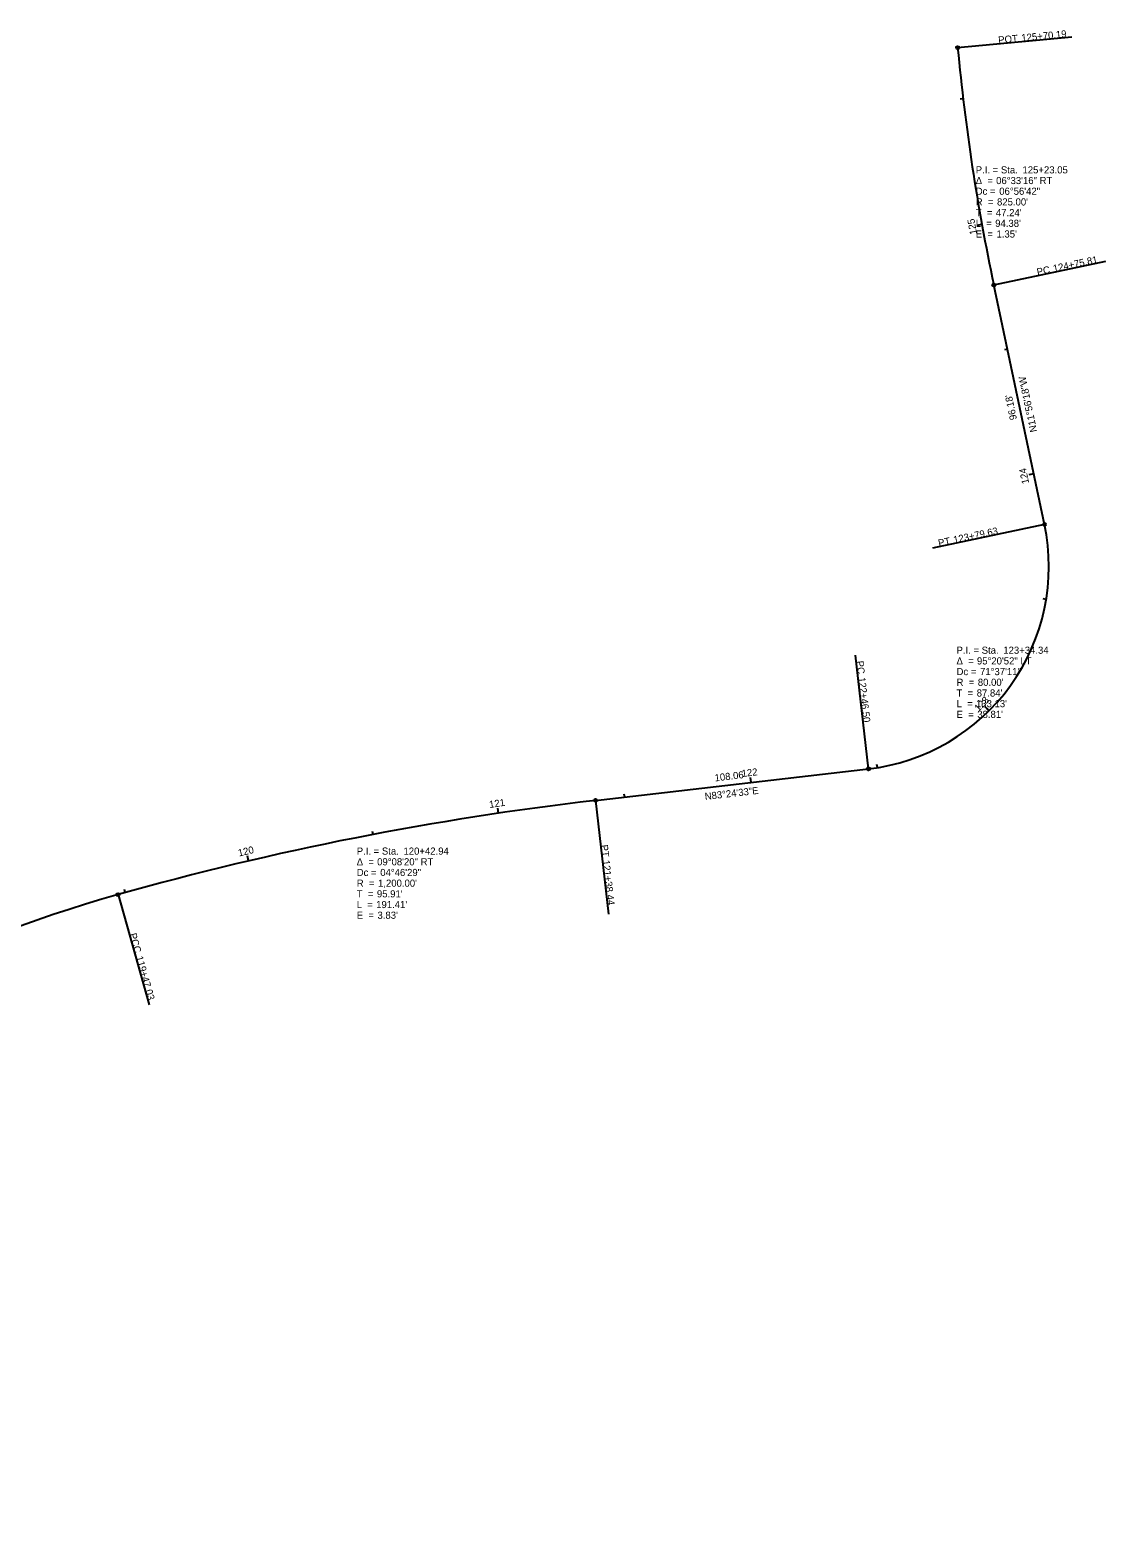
# Model space of a CAD drawing. Extents: x 2325404 to 2326256, y 693508 to 694271.
# Drawn here: x 2325834 to 2326256, y 693678 to 694271 of the extents above; entities that cross this region are included whole.
import ezdxf

# ---------------------------------------------------------------- set-up
doc = ezdxf.new("R2010")
doc.units = 0
for name, color, linetype in [('GE_P_Alignment_100_Bearings', 7, 'Continuous'), ('GE_P_Alignment_100_Cardinal_Points', 7, 'Continuous'), ('GE_P_Alignment_100_Distances', 7, 'Continuous'), ('GE_X_Alignment', 7, 'Continuous'), ('GE_X_Alignment_1000_Curve_Data', 7, 'Continuous'), ('GE_X_Alignment_1000_Stations', 7, 'Continuous'), ('GE_X_Alignment_100_Curve_Data', 7, 'Continuous'), ('GE_X_Alignment_100_Stations', 7, 'Continuous'), ('GE_X_Alignment_500_Curve_Data', 7, 'Continuous'), ('GE_X_Alignment_500_Stations', 7, 'Continuous')]:
    doc.layers.add(name, color=color, linetype=linetype)

msp = doc.modelspace()

# ---------------------------------------------------------------- linework, layer by layer
at = {"layer": 'GE_P_Alignment_100_Cardinal_Points'}
for p, q in [((2326200.23, 694243.59), (2326199.04, 694243.45)), ((2326207.64, 694194.15), (2326205.67, 694193.8)), ((2326207.64, 694194.15), (2326206.46, 694193.94)), ((2326217.64, 694145.16), (2326216.46, 694144.92)), ((2326227.98, 694096.25), (2326226.02, 694095.83)), ((2326227.98, 694096.25), (2326226.81, 694096)), ((2326232.88, 694046.86), (2326231.69, 694047.06)), ((2326166.58, 693980.77), (2326166.39, 693981.96)), ((2326116.92, 693974.96), (2326116.69, 693976.94)), ((2326116.92, 693974.96), (2326116.78, 693976.15)), ((2326067.25, 693969.22), (2326067.11, 693970.41)), ((2326017.65, 693962.87), (2326017.36, 693964.85)), ((2325968.36, 693954.52), (2325968.13, 693955.69)), ((2325968.36, 693954.49), (2325968.13, 693955.69)), ((2325919.46, 693944.11), (2325919, 693946.06)), ((2325871.03, 693931.69), (2325870.71, 693932.84))]:
    msp.add_line(p, q, dxfattribs=at)
at = {"layer": 'GE_X_Alignment'}
for p, q in [((2326232.19, 694076.32), (2326212.3, 694170.42)), ((2326055.76, 693967.89), (2326163.11, 693980.3))]:
    msp.add_line(p, q, dxfattribs=at)
for centre, radius, start, end in [((2327019.45, 694341.07), 825, 185.38408, 191.93842), ((2326153.93, 694059.77), 80, 276.59071, 11.93842), ((2326193.49, 692775.82), 1200, 96.59071, 105.72963), ((2326017.28, 693401.48), 550, 105.72963, 149.7973)]:
    msp.add_arc(centre, radius, start, end, dxfattribs=at)
at = {"layer": 'GE_X_Alignment_1000_Stations'}
for p, q in [((2326198.09, 694263.66), (2326242.9, 694267.89)), ((2326212.3, 694170.42), (2326256.33, 694179.72)), ((2326232.19, 694076.32), (2326188.17, 694067.01)), ((2326163.11, 693980.3), (2326157.94, 694025)), ((2326055.76, 693967.89), (2326060.93, 693923.19)), ((2325868.17, 693930.88), (2325880.37, 693887.57))]:
    msp.add_line(p, q, dxfattribs=at)
for centre in [(2326198.09, 694263.66), (2326212.3, 694170.42), (2326232.19, 694076.32), (2326163.11, 693980.3), (2326055.76, 693967.89), (2325868.17, 693930.88)]:
    msp.add_circle(centre, 0.6, dxfattribs=at)
at = {"layer": 'GE_X_Alignment_100_Stations'}
for p, q in [((2326198.09, 694263.66), (2326242.9, 694267.89)), ((2326207.64, 694194.15), (2326205.67, 694193.8)), ((2326212.3, 694170.42), (2326256.33, 694179.72)), ((2326232.19, 694076.32), (2326188.17, 694067.01)), ((2326163.11, 693980.3), (2326157.94, 694025)), ((2326210.4, 694003.11), (2326208.99, 694004.52)), ((2326055.76, 693967.89), (2326060.93, 693923.19)), ((2325919.46, 693944.11), (2325919, 693946.06)), ((2325868.17, 693930.88), (2325880.37, 693887.57))]:
    msp.add_line(p, q, dxfattribs=at)
for centre in [(2326198.09, 694263.66), (2326212.3, 694170.42), (2326232.19, 694076.32), (2326163.11, 693980.3), (2326055.76, 693967.89), (2325868.17, 693930.88)]:
    msp.add_circle(centre, 0.6, dxfattribs=at)
at = {"layer": 'GE_X_Alignment_500_Stations'}
for p, q in [((2326198.09, 694263.66), (2326242.9, 694267.89)), ((2326212.3, 694170.42), (2326256.33, 694179.72)), ((2326232.19, 694076.32), (2326188.17, 694067.01)), ((2326163.11, 693980.3), (2326157.94, 694025)), ((2326210.4, 694003.11), (2326209.56, 694003.96)), ((2326055.76, 693967.89), (2326060.93, 693923.19)), ((2326017.65, 693962.87), (2326017.48, 693964.06)), ((2325919.46, 693944.11), (2325919, 693946.06)), ((2325868.17, 693930.88), (2325880.37, 693887.57))]:
    msp.add_line(p, q, dxfattribs=at)
for centre in [(2326198.09, 694263.66), (2326212.3, 694170.42), (2326232.19, 694076.32), (2326163.11, 693980.3), (2326055.76, 693967.89), (2325868.17, 693930.88)]:
    msp.add_circle(centre, 0.6, dxfattribs=at)

# ---------------------------------------------------------------- texts
at = {"layer": 'GE_P_Alignment_100_Bearings'}
for s, rotation, p in [('N11°56\'18"W', 101.93842, (2326229.37, 694112.89)), ('N83°24\'33"E', 6.59071, (2326098.88, 693968.04))]:
    msp.add_text(s, height=2.8, rotation=rotation, dxfattribs=at).set_placement(p)
at = {"layer": 'GE_P_Alignment_100_Cardinal_Points'}
for s, rotation, p in [('125', 100.25843, (2326205.72, 694190.46)), ('124', 101.93842, (2326226.2, 694092.56)), ('122', 6.59071, (2326113.38, 693977.07)), ('121', 8.42601, (2326014.21, 693964.89)), ('120', 13.20066, (2325915.68, 693945.84))]:
    msp.add_text(s, height=2.8, rotation=rotation, dxfattribs=at).set_placement(p)
at = {"layer": 'GE_P_Alignment_100_Distances'}
for s, rotation, p in [("96.18'", 101.93842, (2326221.41, 694117.67)), ("108.06'", 6.59071, (2326102.76, 693975.34))]:
    msp.add_text(s, height=2.8, rotation=rotation, dxfattribs=at).set_placement(p)
at = {"layer": 'GE_X_Alignment_1000_Curve_Data'}
for s, p in [('P.I. = Sta. ', (2326205.2, 694214.24)), ('125+23.05', (2326223.57, 694214.24)), ('Δ  = ', (2326205.2, 694210.04)), ('06°33\'16" RT', (2326213.22, 694210.04)), ('Dc = ', (2326205.2, 694205.84)), ('R  = ', (2326205.2, 694201.64)), ("825.00'", (2326213.56, 694201.64)), ('06°56\'42"', (2326214.44, 694205.84)), ('T  = ', (2326205.2, 694197.44)), ("47.24'", (2326213.13, 694197.44)), ('L  = ', (2326205.2, 694193.24)), ("94.38'", (2326212.84, 694193.24)), ("1.35'", (2326213.35, 694189.04)), ('E  = ', (2326205.2, 694189.04)), ('P.I. = Sta. ', (2326197.65, 694025.51)), ('123+34.34', (2326216.02, 694025.51)), ('Δ  = ', (2326197.65, 694021.31)), ('95°20\'52" LT', (2326205.67, 694021.31)), ('Dc = ', (2326197.65, 694017.11)), ('R  = ', (2326197.65, 694012.91)), ("80.00'", (2326206.02, 694012.91)), ('71°37\'11"', (2326206.89, 694017.11)), ('T  = ', (2326197.65, 694008.71)), ("87.84'", (2326205.58, 694008.71)), ('L  = ', (2326197.65, 694004.51)), ('E  = ', (2326197.65, 694000.31)), ("133.13'", (2326205.3, 694004.51)), ("38.81'", (2326205.8, 694000.31)), ('P.I. = Sta. ', (2325961.97, 693946.59)), ('120+42.94', (2325980.34, 693946.59)), ('Δ  = ', (2325961.97, 693942.39)), ('09°08\'20" RT', (2325969.99, 693942.39)), ('Dc = ', (2325961.97, 693938.19)), ('04°46\'29"', (2325971.21, 693938.19)), ('T  = ', (2325961.97, 693929.79)), ('R  = ', (2325961.97, 693933.99)), ("95.91'", (2325969.9, 693929.79)), ("1,200.00'", (2325970.34, 693933.99)), ('L  = ', (2325961.97, 693925.59)), ("191.41'", (2325969.61, 693925.59)), ('E  = ', (2325961.97, 693921.39)), ("3.83'", (2325970.12, 693921.39))]:
    msp.add_text(s, height=2.8, dxfattribs=at).set_placement(p)
at = {"layer": 'GE_X_Alignment_1000_Stations'}
for s, rotation, p in [('125+70.19', 5.38408, (2326223.26, 694266.08)), ('POT', 5.38408, (2326214.17, 694265.23)), ('124+75.81', 11.93842, (2326235.88, 694175.45)), ('PC', 11.93842, (2326229.5, 694174.1)), ('123+79.63', 11.93842, (2326196.71, 694068.86)), ('PT', 11.93842, (2326190.76, 694067.6)), ('PC', 276.59071, (2326158.27, 694022.59)), ('122+46.50', 276.59071, (2326159.02, 694016.12)), ('PT', 276.59071, (2326057.84, 693950.33)), ('121+38.44', 276.59071, (2326058.54, 693944.28)), ('PCC', 285.72963, (2325872.6, 693915.33)), ('119+47.03', 285.72963, (2325875.14, 693906.33))]:
    msp.add_text(s, height=2.8, rotation=rotation, dxfattribs=at).set_placement(p)
at = {"layer": 'GE_X_Alignment_100_Curve_Data'}
for s, p in [('P.I. = Sta. ', (2326205.2, 694214.24)), ('125+23.05', (2326223.57, 694214.24)), ('Δ  = ', (2326205.2, 694210.04)), ('06°33\'16" RT', (2326213.22, 694210.04)), ('Dc = ', (2326205.2, 694205.84)), ('R  = ', (2326205.2, 694201.64)), ("825.00'", (2326213.56, 694201.64)), ('06°56\'42"', (2326214.44, 694205.84)), ('T  = ', (2326205.2, 694197.44)), ("47.24'", (2326213.13, 694197.44)), ('L  = ', (2326205.2, 694193.24)), ("94.38'", (2326212.84, 694193.24)), ("1.35'", (2326213.35, 694189.04)), ('E  = ', (2326205.2, 694189.04)), ('P.I. = Sta. ', (2326197.65, 694025.51)), ('123+34.34', (2326216.02, 694025.51)), ('Δ  = ', (2326197.65, 694021.31)), ('95°20\'52" LT', (2326205.67, 694021.31)), ('Dc = ', (2326197.65, 694017.11)), ('R  = ', (2326197.65, 694012.91)), ("80.00'", (2326206.02, 694012.91)), ('71°37\'11"', (2326206.89, 694017.11)), ('T  = ', (2326197.65, 694008.71)), ("87.84'", (2326205.58, 694008.71)), ('L  = ', (2326197.65, 694004.51)), ('E  = ', (2326197.65, 694000.31)), ("133.13'", (2326205.3, 694004.51)), ("38.81'", (2326205.8, 694000.31)), ('P.I. = Sta. ', (2325961.97, 693946.59)), ('120+42.94', (2325980.34, 693946.59)), ('Δ  = ', (2325961.97, 693942.39)), ('09°08\'20" RT', (2325969.99, 693942.39)), ('Dc = ', (2325961.97, 693938.19)), ('04°46\'29"', (2325971.21, 693938.19)), ('T  = ', (2325961.97, 693929.79)), ('R  = ', (2325961.97, 693933.99)), ("95.91'", (2325969.9, 693929.79)), ("1,200.00'", (2325970.34, 693933.99)), ('L  = ', (2325961.97, 693925.59)), ("191.41'", (2325969.61, 693925.59)), ('E  = ', (2325961.97, 693921.39)), ("3.83'", (2325970.12, 693921.39))]:
    msp.add_text(s, height=2.8, dxfattribs=at).set_placement(p)
at = {"layer": 'GE_X_Alignment_100_Stations'}
for s, rotation, p in [('125+70.19', 5.38408, (2326223.26, 694266.08)), ('POT', 5.38408, (2326214.17, 694265.23)), ('125', 100.25843, (2326205.72, 694190.46)), ('124+75.81', 11.93842, (2326235.88, 694175.45)), ('PC', 11.93842, (2326229.5, 694174.1)), ('N11°56\'18"W', 101.93842, (2326229.37, 694112.89)), ("96.18'", 101.93842, (2326221.41, 694117.67)), ('123+79.63', 11.93842, (2326196.71, 694068.86)), ('PT', 11.93842, (2326190.76, 694067.6)), ('PC', 276.59071, (2326158.27, 694022.59)), ('122+46.50', 276.59071, (2326159.02, 694016.12)), ('123', 44.90792, (2326206.29, 694002.61)), ("108.06'", 6.59071, (2326102.76, 693975.34)), ('N83°24\'33"E', 6.59071, (2326098.88, 693968.04)), ('120', 13.20066, (2325915.68, 693945.84)), ('PT', 276.59071, (2326057.84, 693950.33)), ('121+38.44', 276.59071, (2326058.54, 693944.28)), ('PCC', 285.72963, (2325872.6, 693915.33)), ('119+47.03', 285.72963, (2325875.14, 693906.33))]:
    msp.add_text(s, height=2.8, rotation=rotation, dxfattribs=at).set_placement(p)
at = {"layer": 'GE_X_Alignment_500_Curve_Data'}
for s, p in [('P.I. = Sta. ', (2326205.2, 694214.24)), ('125+23.05', (2326223.57, 694214.24)), ('Δ  = ', (2326205.2, 694210.04)), ('06°33\'16" RT', (2326213.22, 694210.04)), ('Dc = ', (2326205.2, 694205.84)), ('R  = ', (2326205.2, 694201.64)), ("825.00'", (2326213.56, 694201.64)), ('06°56\'42"', (2326214.44, 694205.84)), ('T  = ', (2326205.2, 694197.44)), ("47.24'", (2326213.13, 694197.44)), ('L  = ', (2326205.2, 694193.24)), ("94.38'", (2326212.84, 694193.24)), ("1.35'", (2326213.35, 694189.04)), ('E  = ', (2326205.2, 694189.04)), ('P.I. = Sta. ', (2326197.65, 694025.51)), ('123+34.34', (2326216.02, 694025.51)), ('Δ  = ', (2326197.65, 694021.31)), ('95°20\'52" LT', (2326205.67, 694021.31)), ('Dc = ', (2326197.65, 694017.11)), ('R  = ', (2326197.65, 694012.91)), ("80.00'", (2326206.02, 694012.91)), ('71°37\'11"', (2326206.89, 694017.11)), ('T  = ', (2326197.65, 694008.71)), ("87.84'", (2326205.58, 694008.71)), ('L  = ', (2326197.65, 694004.51)), ('E  = ', (2326197.65, 694000.31)), ("133.13'", (2326205.3, 694004.51)), ("38.81'", (2326205.8, 694000.31)), ('P.I. = Sta. ', (2325961.97, 693946.59)), ('120+42.94', (2325980.34, 693946.59)), ('Δ  = ', (2325961.97, 693942.39)), ('09°08\'20" RT', (2325969.99, 693942.39)), ('Dc = ', (2325961.97, 693938.19)), ('04°46\'29"', (2325971.21, 693938.19)), ('T  = ', (2325961.97, 693929.79)), ('R  = ', (2325961.97, 693933.99)), ("95.91'", (2325969.9, 693929.79)), ("1,200.00'", (2325970.34, 693933.99)), ('L  = ', (2325961.97, 693925.59)), ("191.41'", (2325969.61, 693925.59)), ('E  = ', (2325961.97, 693921.39)), ("3.83'", (2325970.12, 693921.39))]:
    msp.add_text(s, height=2.8, dxfattribs=at).set_placement(p)
at = {"layer": 'GE_X_Alignment_500_Stations'}
for s, rotation, p in [('125+70.19', 5.38408, (2326223.26, 694266.08)), ('POT', 5.38408, (2326214.17, 694265.23)), ('124+75.81', 11.93842, (2326235.88, 694175.45)), ('PC', 11.93842, (2326229.5, 694174.1)), ('N11°56\'18"W', 101.93842, (2326229.37, 694112.89)), ("96.18'", 101.93842, (2326221.41, 694117.67)), ('123+79.63', 11.93842, (2326196.71, 694068.86)), ('PT', 11.93842, (2326190.76, 694067.6)), ('PC', 276.59071, (2326158.27, 694022.59)), ('122+46.50', 276.59071, (2326159.02, 694016.12)), ("108.06'", 6.59071, (2326102.76, 693975.34)), ('N83°24\'33"E', 6.59071, (2326098.88, 693968.04)), ('120', 13.20066, (2325915.68, 693945.84)), ('PT', 276.59071, (2326057.84, 693950.33)), ('121+38.44', 276.59071, (2326058.54, 693944.28)), ('PCC', 285.72963, (2325872.6, 693915.33)), ('119+47.03', 285.72963, (2325875.14, 693906.33))]:
    msp.add_text(s, height=2.8, rotation=rotation, dxfattribs=at).set_placement(p)

doc.saveas('drawing.dxf')
